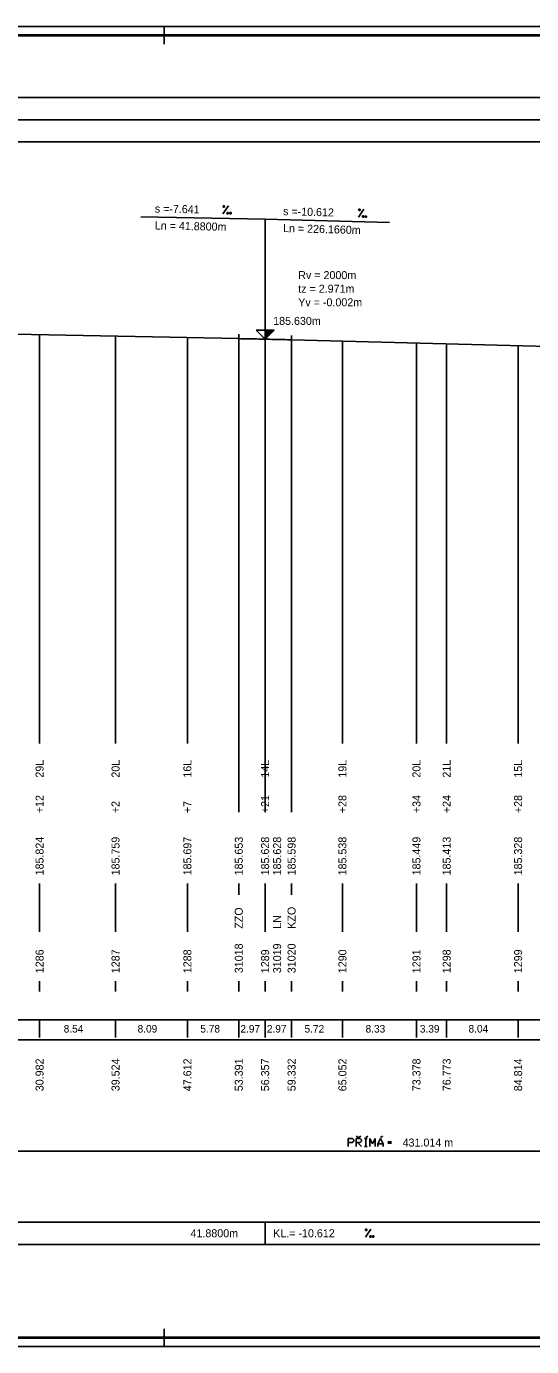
# Model space of a CAD drawing. Extents: x 0 to 10087, y -805 to 297.
# Drawn here: x 1439 to 1552.7, y 0 to 297 of the extents above; entities that cross this region are included whole.
import ezdxf

# ---------------------------------------------------------------- set-up
doc = ezdxf.new("R2010")
doc.units = 0
for name, color, linetype in [('CARKY_HODNOT', 7, 'Continuous'), ('KRIV1_CARA', 7, 'Continuous'), ('KRIV1_TEXT', 7, 'Continuous'), ('NIVELETA_CARA', 7, 'Continuous'), ('NIVELETA_TEXT', 7, 'Continuous'), ('RAM', 7, 'Continuous'), ('STAN_CARA', 7, 'Continuous'), ('STAN_PAS', 7, 'Continuous'), ('STAN_TEXT', 7, 'Continuous'), ('TEXT', 7, 'Continuous'), ('TXT_C_BODU', 7, 'Continuous')]:
    doc.layers.add(name, color=color, linetype=linetype)

msp = doc.modelspace()

# ---------------------------------------------------------------- linework, layer by layer
at = {"layer": 'CARKY_HODNOT'}
for p, q in [((1441.96, 138.35), (1441.96, 227.62)), ((1459.05, 138.35), (1459.05, 227.29)), ((1475.22, 138.35), (1475.22, 226.98)), ((1486.78, 138.35), (1486.78, 226.76)), ((1492.71, 138.35), (1492.71, 226.64)), ((1492.72, 138.35), (1492.72, 226.64)), ((1498.66, 138.35), (1498.66, 226.49)), ((1510.1, 138.35), (1510.1, 226.19)), ((1526.76, 138.35), (1526.76, 225.75)), ((1533.55, 138.35), (1533.55, 225.57)), ((1549.63, 138.35), (1549.63, 225.14)), ((1441.96, 135.65), (1441.96, 138.35)), ((1459.05, 135.65), (1459.05, 138.35)), ((1475.22, 135.65), (1475.22, 138.35)), ((1486.78, 126.2), (1486.78, 138.35)), ((1492.71, 135.65), (1492.71, 138.35)), ((1492.72, 126.2), (1492.72, 138.35)), ((1498.66, 126.2), (1498.66, 138.35)), ((1510.1, 135.65), (1510.1, 138.35)), ((1526.76, 135.65), (1526.76, 138.35)), ((1533.55, 135.65), (1533.55, 138.35)), ((1549.63, 135.65), (1549.63, 138.35)), ((1486.78, 120.25), (1486.78, 126.2)), ((1492.72, 120.25), (1492.72, 126.2)), ((1498.66, 120.25), (1498.66, 126.2)), ((1441.96, 93.3), (1441.96, 104.2)), ((1459.05, 93.3), (1459.05, 104.2)), ((1475.22, 93.3), (1475.22, 104.2)), ((1486.78, 101.65), (1486.78, 104.2)), ((1492.71, 93.3), (1492.71, 104.2)), ((1492.72, 100), (1492.72, 104.2)), ((1498.66, 101.65), (1498.66, 104.2)), ((1510.1, 93.3), (1510.1, 104.2)), ((1526.76, 93.3), (1526.76, 104.2)), ((1533.55, 93.3), (1533.55, 104.2)), ((1549.63, 93.3), (1549.63, 104.2)), ((1441.96, 79.9), (1441.96, 82.2)), ((1459.05, 79.9), (1459.05, 82.2)), ((1475.22, 79.9), (1475.22, 82.2)), ((1486.78, 79.9), (1486.78, 82.2)), ((1492.71, 79.9), (1492.71, 82.2)), ((1492.72, 79.9), (1492.72, 82.2)), ((1498.66, 79.9), (1498.66, 82.2)), ((1510.1, 79.9), (1510.1, 82.2)), ((1526.76, 79.9), (1526.76, 82.2)), ((1533.55, 79.9), (1533.55, 82.2)), ((1549.63, 79.9), (1549.63, 82.2))]:
    msp.add_line(p, q, dxfattribs=at)
at = {"layer": 'KRIV1_CARA'}
msp.add_line((1094.43, 44), (1956.46, 44), dxfattribs=at)
at = {"layer": 'KRIV1_TEXT'}
for p, q in [((1511.42, 45), (1511.42, 46.8)), ((1511.42, 46.8), (1512.33, 46.8)), ((1512.32, 45.9), (1511.42, 45.9)), ((1512.64, 46.2), (1512.32, 45.9)), ((1512.33, 46.8), (1512.64, 46.49)), ((1512.64, 46.49), (1512.64, 46.2)), ((1513.7, 47.03), (1513.19, 47.37)), ((1513.22, 45), (1513.22, 46.8)), ((1513.22, 46.8), (1514.12, 46.8)), ((1514.12, 45.9), (1513.22, 45.9)), ((1513.52, 45.9), (1514.42, 45)), ((1513.7, 47.03), (1514.22, 47.37)), ((1514.12, 46.8), (1514.42, 46.51)), ((1514.42, 46.2), (1514.12, 45.9)), ((1514.42, 46.51), (1514.42, 46.2)), ((1515.06, 46.79), (1515.63, 46.79)), ((1515.06, 45), (1515.63, 45)), ((1515.34, 47.03), (1515.85, 47.37)), ((1515.34, 45), (1515.34, 46.79)), ((1516.23, 45), (1516.23, 46.79)), ((1516.23, 46.79), (1516.85, 45.6)), ((1516.85, 45.6), (1517.43, 46.79)), ((1517.43, 46.79), (1517.43, 45)), ((1518.63, 46.81), (1518.03, 45.6)), ((1518.03, 45), (1518.03, 45.6)), ((1518.03, 45.6), (1519.23, 45.6)), ((1519.23, 45.6), (1518.63, 46.81)), ((1518.65, 47.03), (1519.16, 47.37)), ((1519.23, 45.6), (1519.23, 45)), ((1520.35, 46.07), (1521.16, 46.07)), ((1520.35, 45.75), (1521.16, 45.75))]:
    msp.add_line(p, q, dxfattribs=at)
at = {"layer": 'NIVELETA_CARA'}
for p, q in [((300, 281), (8321.33, 281)), ((300, 276), (8321.33, 276)), ((300, 271), (8321.33, 271)), ((1492.72, 253.65), (1464.72, 254.18)), ((1492.72, 226.65), (1492.72, 253.65)), ((1492.72, 253.65), (1520.72, 252.91)), ((1420.55, 228.03), (1486.78, 226.76)), ((1486.78, 226.76), (1486.78, 227.76)), ((1486.78, 226.76), (1492.72, 226.65)), ((1486.78, 226.76), (1487.28, 226.75)), ((1487.28, 226.75), (1487.78, 226.74)), ((1487.78, 226.74), (1488.28, 226.73)), ((1488.28, 226.73), (1488.78, 226.72)), ((1488.78, 226.72), (1489.28, 226.71)), ((1489.28, 226.71), (1489.78, 226.7)), ((1489.78, 226.7), (1490.28, 226.69)), ((1490.28, 226.69), (1490.78, 226.68)), ((1492.72, 226.65), (1490.72, 228.65)), ((1490.72, 228.65), (1494.72, 228.65)), ((1490.78, 226.68), (1491.28, 226.67)), ((1491.28, 226.67), (1491.78, 226.66)), ((1491.78, 226.66), (1492.28, 226.65)), ((1492.28, 226.65), (1492.72, 226.64)), ((1492.72, 226.65), (1492.72, 228.65)), ((1494.72, 228.65), (1492.72, 226.65)), ((1492.72, 226.65), (1498.66, 226.49)), ((1492.72, 226.64), (1493.22, 226.63)), ((1492.79, 226.72), (1492.79, 228.65)), ((1492.86, 226.78), (1492.86, 228.65)), ((1492.92, 226.85), (1492.92, 228.65)), ((1492.99, 226.92), (1492.99, 228.65)), ((1493.06, 226.98), (1493.06, 228.65)), ((1493.12, 227.05), (1493.12, 228.65)), ((1493.19, 227.12), (1493.19, 228.65)), ((1493.22, 226.63), (1493.72, 226.62)), ((1493.26, 227.18), (1493.26, 228.65)), ((1493.32, 227.25), (1493.32, 228.65)), ((1493.39, 227.32), (1493.39, 228.65)), ((1493.46, 227.38), (1493.46, 228.65)), ((1493.52, 227.45), (1493.52, 228.65)), ((1493.59, 227.52), (1493.59, 228.65)), ((1493.66, 227.58), (1493.66, 228.65)), ((1493.72, 227.65), (1493.72, 228.65)), ((1493.72, 226.62), (1494.22, 226.6)), ((1493.79, 227.72), (1493.79, 228.65)), ((1493.86, 227.78), (1493.86, 228.65)), ((1493.92, 227.85), (1493.92, 228.65)), ((1493.99, 227.92), (1493.99, 228.65)), ((1494.06, 227.98), (1494.06, 228.65)), ((1494.12, 228.05), (1494.12, 228.65)), ((1494.19, 228.12), (1494.19, 228.65)), ((1494.22, 226.6), (1494.72, 226.59)), ((1494.26, 228.18), (1494.26, 228.65)), ((1494.32, 228.25), (1494.32, 228.65)), ((1494.39, 228.32), (1494.39, 228.65)), ((1494.46, 228.38), (1494.46, 228.65)), ((1494.52, 228.45), (1494.52, 228.65)), ((1494.59, 228.52), (1494.59, 228.65)), ((1494.66, 228.58), (1494.66, 228.65)), ((1494.72, 226.59), (1495.22, 226.58)), ((1495.22, 226.58), (1495.72, 226.57)), ((1495.72, 226.57), (1496.22, 226.56)), ((1496.22, 226.56), (1496.72, 226.54)), ((1496.72, 226.54), (1497.22, 226.53)), ((1497.22, 226.53), (1497.72, 226.52)), ((1497.72, 226.52), (1498.22, 226.5)), ((1498.22, 226.5), (1498.66, 226.49)), ((1498.66, 226.49), (1498.66, 227.49)), ((1498.66, 226.49), (1929.51, 215.06)), ((500, 28), (8321.33, 28)), ((1492.72, 23), (1492.72, 28)), ((500, 23), (8321.33, 23))]:
    msp.add_line(p, q, dxfattribs=at)
at = {"layer": 'NIVELETA_TEXT'}
for p, q in [((1483.22, 254.84), (1484.44, 256.6)), ((1483.26, 256.63), (1483.25, 256.33)), ((1483.25, 256.33), (1483.55, 256.33)), ((1483.55, 256.62), (1483.26, 256.63)), ((1483.26, 256.63), (1483.26, 256.62)), ((1483.55, 256.33), (1483.55, 256.62)), ((1513.72, 254.1), (1514.95, 255.86)), ((1513.77, 255.89), (1513.76, 255.59)), ((1513.76, 255.59), (1514.06, 255.58)), ((1514.06, 255.88), (1513.77, 255.89)), ((1513.77, 255.89), (1513.77, 255.88)), ((1514.06, 255.58), (1514.06, 255.88)), ((1484.14, 255.11), (1484.13, 254.82)), ((1484.13, 254.82), (1484.43, 254.81)), ((1484.43, 255.11), (1484.14, 255.11)), ((1484.14, 255.11), (1484.14, 255.11)), ((1484.43, 254.81), (1484.43, 255.11)), ((1484.75, 255.1), (1484.74, 254.81)), ((1484.74, 254.81), (1485.04, 254.8)), ((1484.76, 255.1), (1484.75, 255.1)), ((1485.05, 255.1), (1484.76, 255.1)), ((1485.04, 254.8), (1485.05, 255.1)), ((1514.64, 254.37), (1514.63, 254.07)), ((1514.64, 254.37), (1514.63, 254.36)), ((1514.63, 254.07), (1514.92, 254.06)), ((1514.93, 254.36), (1514.64, 254.37)), ((1514.92, 254.06), (1514.93, 254.36)), ((1515.25, 254.35), (1515.24, 254.06)), ((1515.24, 254.06), (1515.54, 254.05)), ((1515.55, 254.34), (1515.25, 254.35)), ((1515.25, 254.35), (1515.25, 254.35)), ((1515.54, 254.05), (1515.55, 254.34)), ((1515.32, 24.6), (1516.51, 26.4)), ((1515.32, 26.4), (1515.32, 26.1)), ((1515.33, 26.4), (1515.32, 26.39)), ((1515.32, 26.1), (1515.62, 26.1)), ((1515.62, 26.4), (1515.33, 26.4)), ((1515.62, 26.1), (1515.62, 26.4)), ((1516.23, 24.9), (1516.23, 24.6)), ((1516.24, 24.9), (1516.23, 24.89)), ((1516.23, 24.6), (1516.53, 24.6)), ((1516.53, 24.9), (1516.24, 24.9)), ((1516.53, 24.6), (1516.53, 24.9)), ((1516.85, 24.9), (1516.85, 24.6)), ((1517.14, 24.9), (1516.85, 24.9)), ((1516.85, 24.9), (1516.85, 24.89)), ((1516.85, 24.6), (1517.14, 24.6)), ((1517.14, 24.6), (1517.14, 24.9))]:
    msp.add_line(p, q, dxfattribs=at)
at = {"layer": 'RAM'}
for p, q in [((8636.33, 297), (0, 297)), ((1470, 293), (1470, 297)), ((8634.33, 295.1), (2, 295.1)), ((8634.33, 295), (2, 295)), ((8634.33, 294.9), (2, 294.9)), ((1470, 0), (1470, 4)), ((0, 0), (8636.33, 0)), ((2, 2.1), (8634.33, 2.1)), ((2, 2), (8634.33, 2)), ((2, 1.9), (8634.33, 1.9))]:
    msp.add_line(p, q, dxfattribs=at)
at = {"layer": 'STAN_CARA'}
msp.add_line((1381.5, 69), (1579, 69), dxfattribs=at)
at = {"layer": 'STAN_PAS'}
for p, q in [((300, 73.5), (8321.33, 73.5)), ((1441.96, 69.5), (1441.96, 73.5)), ((1459.05, 69.5), (1459.05, 73.5)), ((1475.22, 69.5), (1475.22, 73.5)), ((1486.78, 69.5), (1486.78, 73.5)), ((1492.71, 69.5), (1492.71, 73.5)), ((1492.72, 69.5), (1492.72, 73.5)), ((1498.66, 69.5), (1498.66, 73.5)), ((1510.1, 69.5), (1510.1, 73.5)), ((1526.76, 69.5), (1526.76, 73.5)), ((1533.55, 69.5), (1533.55, 73.5)), ((1549.63, 69.5), (1549.63, 73.5))]:
    msp.add_line(p, q, dxfattribs=at)

# ---------------------------------------------------------------- texts
at = {"layer": 'KRIV1_TEXT'}
msp.add_text(' 431.014 m', height=1.8, dxfattribs=at).set_placement((1522.97, 45))
at = {"layer": 'NIVELETA_TEXT'}
for s, rotation, p in [('s =-7.641', 358.9057, (1467.87, 255.12)), ('s =-10.612', 358.4803, (1496.72, 254.54)), ('Ln = 41.8800m', 358.9057, (1467.87, 251.32)), ('Ln = 226.1660m', 358.4803, (1496.72, 250.74))]:
    msp.add_text(s, height=1.8, rotation=rotation, dxfattribs=at).set_placement(p)
for s, p in [('Rv = 2000m', (1500.16, 240.15)), ('tz = 2.971m', (1500.16, 237.09)), ('Yv = -0.002m', (1500.16, 234.03)), ('185.630m', (1494.52, 229.85)), ('41.8800m', (1475.92, 24.6)), ('KL.= -10.612', (1494.52, 24.6))]:
    msp.add_text(s, height=1.8, dxfattribs=at).set_placement(p)
at = {"layer": 'STAN_TEXT'}
for s, p in [('8.54', (1447.39, 70.65)), ('8.09', (1464.02, 70.65)), ('5.78', (1478.13, 70.65)), ('2.97', (1487.15, 70.64)), ('2.97', (1493.1, 70.65)), ('5.72', (1501.57, 70.64)), ('8.33', (1515.31, 70.65)), ('3.39', (1527.52, 70.64)), ('8.04', (1538.47, 70.65))]:
    msp.add_text(s, height=1.7, dxfattribs=at).set_placement(p)
for s, p in [('30.982', (1442.86, 57.45)), ('39.524', (1459.95, 57.45)), ('47.612', (1476.12, 57.45)), ('53.391', (1487.68, 57.45)), ('56.357', (1493.61, 57.45)), ('59.332', (1499.56, 57.45)), ('65.052', (1511, 57.45)), ('73.378', (1527.66, 57.45)), ('76.773', (1534.45, 57.45)), ('84.814', (1550.53, 57.45))]:
    msp.add_text(s, height=1.8, rotation=90, dxfattribs=at).set_placement(p)
at = {"layer": 'TEXT'}
for s, p in [('29L', (1442.86, 128)), ('20L', (1459.95, 128)), ('16L', (1476.12, 128)), ('14L', (1493.61, 128)), ('19L', (1511, 128)), ('20L', (1527.66, 128)), ('21L', (1534.45, 128)), ('15L', (1550.53, 128)), ('+12', (1442.86, 120)), ('+2', (1459.95, 120)), ('+7', (1476.12, 120)), ('+21', (1493.61, 120)), ('+28', (1511, 120)), ('+34', (1527.66, 120)), ('+24', (1534.45, 120)), ('+28', (1550.53, 120)), ('185.824', (1442.86, 106)), ('185.759', (1459.95, 106)), ('185.697', (1476.12, 106)), ('185.653', (1487.68, 106)), ('185.628', (1493.61, 106)), ('185.628', (1496.31, 106)), ('185.598', (1499.56, 106)), ('185.538', (1511, 106)), ('185.449', (1527.66, 106)), ('185.413', (1534.45, 106)), ('185.328', (1550.53, 106)), ('ZZO', (1487.68, 94)), ('KZO', (1499.56, 94)), ('LN', (1496.31, 94))]:
    msp.add_text(s, height=1.8, rotation=90, dxfattribs=at).set_placement(p)
at = {"layer": 'TXT_C_BODU'}
for s, p in [('1286', (1442.86, 84)), ('1287', (1459.95, 84)), ('1288', (1476.12, 84)), ('31018', (1487.68, 84)), ('1289', (1493.61, 84)), ('31019', (1496.31, 84)), ('31020', (1499.56, 84)), ('1290', (1511, 84)), ('1291', (1527.66, 84)), ('1298', (1534.45, 84)), ('1299', (1550.53, 84))]:
    msp.add_text(s, height=1.8, rotation=90, dxfattribs=at).set_placement(p)

doc.saveas('drawing.dxf')
